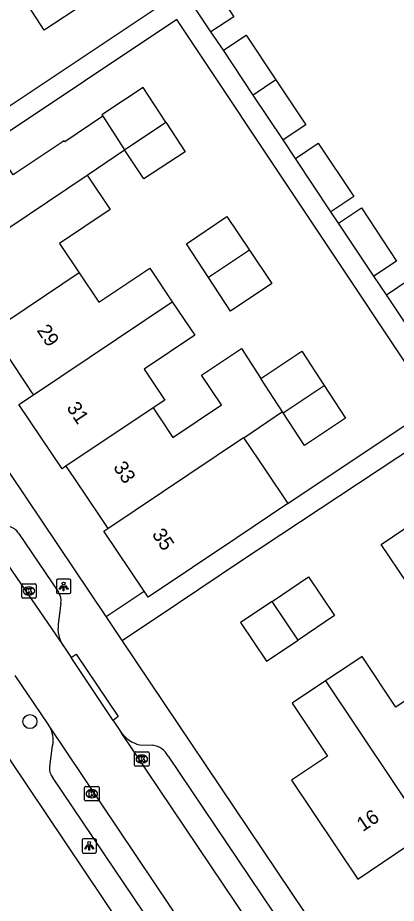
# Model space of a CAD drawing. Extents: x 158352 to 159489, y 383828 to 384597.
# Drawn here: x 158808.6 to 158835, y 384309.4 to 384371.1 of the extents above; entities that cross this region are included whole.
import ezdxf

# ---------------------------------------------------------------- set-up
doc = ezdxf.new("R2010")
doc.units = 0
for name, color, linetype in [('IMGEO_Boom', 7, 'Continuous'), ('IMGEO_Kolk', 7, 'Continuous'), ('IMGEO_Lichtpunt', 7, 'Continuous'), ('IMGEO_Pand', 7, 'Continuous'), ('IMGEO_Pand_nummerreeks', 7, 'Continuous'), ('IMGEO_Rijbaan_lokaal_open', 7, 'Continuous'), ('IMGEO_Voetpad_open', 7, 'Continuous')]:
    doc.layers.add(name, color=color, linetype=linetype)

msp = doc.modelspace()

# ---------------------------------------------------------------- linework, layer by layer
at = {"layer": 'IMGEO_Boom'}
msp.add_circle((158809.47, 384322.081), 0.489, dxfattribs=at)
at = {"layer": 'IMGEO_Kolk'}
for p, q in [((158808.897, 384330.753), (158808.897, 384331.605)), ((158808.972, 384331.679), (158809.824, 384331.679)), ((158809.385, 384331.459), (158809.41, 384331.459)), ((158809.898, 384331.605), (158809.898, 384330.753)), ((158809.824, 384330.679), (158808.972, 384330.679)), ((158809.408, 384330.899), (158809.383, 384330.899)), ((158816.753, 384319.045), (158816.753, 384319.897)), ((158816.828, 384319.971), (158817.68, 384319.971)), ((158817.241, 384319.751), (158817.266, 384319.751)), ((158817.754, 384319.897), (158817.754, 384319.045)), ((158817.68, 384318.971), (158816.828, 384318.971)), ((158817.264, 384319.191), (158817.239, 384319.191)), ((158813.273, 384316.63), (158813.273, 384317.482)), ((158813.348, 384317.556), (158814.2, 384317.556)), ((158813.761, 384317.336), (158813.786, 384317.336)), ((158814.274, 384317.482), (158814.274, 384316.63)), ((158814.2, 384316.556), (158813.348, 384316.556)), ((158813.784, 384316.776), (158813.759, 384316.776))]:
    msp.add_line(p, q, dxfattribs=at)
for points in [[(158808.897, 384330.753), (158808.897, 384331.605)], [(158808.972, 384331.679), (158809.824, 384331.679)], [(158809.218, 384331.379), (158809.341, 384331.379), (158809.341, 384331.228), (158809.471, 384331.379), (158809.635, 384331.379), (158809.489, 384331.228), (158809.642, 384330.979), (158809.49, 384330.979), (158809.405, 384331.143), (158809.341, 384331.076), (158809.341, 384330.979), (158809.218, 384330.979), (158809.218, 384331.379)], [(158809.898, 384331.605), (158809.898, 384330.753)], [(158809.824, 384330.679), (158808.972, 384330.679)], [(158816.753, 384319.045), (158816.753, 384319.897)], [(158816.828, 384319.971), (158817.68, 384319.971)], [(158817.074, 384319.671), (158817.197, 384319.671), (158817.197, 384319.52), (158817.327, 384319.671), (158817.491, 384319.671), (158817.345, 384319.52), (158817.498, 384319.271), (158817.346, 384319.271), (158817.261, 384319.435), (158817.197, 384319.368), (158817.197, 384319.271), (158817.074, 384319.271), (158817.074, 384319.671)], [(158817.754, 384319.897), (158817.754, 384319.045)], [(158817.68, 384318.971), (158816.828, 384318.971)], [(158813.273, 384316.63), (158813.273, 384317.482)], [(158813.348, 384317.556), (158814.2, 384317.556)], [(158813.594, 384317.256), (158813.717, 384317.256), (158813.717, 384317.105), (158813.847, 384317.256), (158814.011, 384317.256), (158813.865, 384317.105), (158814.018, 384316.856), (158813.866, 384316.856), (158813.781, 384317.02), (158813.717, 384316.953), (158813.717, 384316.856), (158813.594, 384316.856), (158813.594, 384317.256)], [(158814.274, 384317.482), (158814.274, 384316.63)], [(158814.2, 384316.556), (158813.348, 384316.556)]]:
    msp.add_lwpolyline(points, dxfattribs=at)
for centre, start, end in [((158808.974, 384331.603), 91.55205, 178.44795), ((158808.974, 384331.603), 91.55205, 178.44795), ((158809.822, 384331.603), 1.55205, 88.44795), ((158809.822, 384331.603), 1.55205, 88.44795), ((158808.974, 384330.755), 181.55205, 268.44795), ((158808.974, 384330.755), 181.55205, 268.44795), ((158809.822, 384330.755), 271.55205, 358.44795), ((158809.822, 384330.755), 271.55205, 358.44795), ((158816.83, 384319.895), 91.55205, 178.44795), ((158816.83, 384319.895), 91.55205, 178.44795), ((158817.678, 384319.895), 1.55205, 88.44795), ((158817.678, 384319.895), 1.55205, 88.44795), ((158816.83, 384319.047), 181.55205, 268.44795), ((158816.83, 384319.047), 181.55205, 268.44795), ((158817.678, 384319.047), 271.55205, 358.44795), ((158817.678, 384319.047), 271.55205, 358.44795), ((158813.35, 384317.48), 91.55205, 178.44795), ((158813.35, 384317.48), 91.55205, 178.44795), ((158814.198, 384317.48), 1.55205, 88.44795), ((158814.198, 384317.48), 1.55205, 88.44795), ((158813.35, 384316.632), 181.55205, 268.44795), ((158813.35, 384316.632), 181.55205, 268.44795), ((158814.198, 384316.632), 271.55205, 358.44795), ((158814.198, 384316.632), 271.55205, 358.44795)]:
    msp.add_arc(centre, 0.0765, start, end, dxfattribs=at)
for centre, major_axis, ratio, start_param, end_param in [((158809.384, 384331.179), (-0.387, 0.002), 0.722429, 4.712389, 7.853982), ((158809.409, 384331.179), (-0.39, 0.002), 0.717154, 1.570796, 4.712389), ((158817.24, 384319.471), (-0.387, 0.002), 0.722429, 4.712389, 7.853982), ((158817.265, 384319.471), (-0.39, 0.002), 0.717154, 1.570796, 4.712389), ((158813.76, 384317.056), (-0.387, 0.002), 0.722429, 4.712389, 7.853982), ((158813.785, 384317.056), (-0.39, 0.002), 0.717154, 1.570796, 4.712389)]:
    msp.add_ellipse(centre, major_axis=major_axis, ratio=ratio, start_param=start_param, end_param=end_param, dxfattribs=at)
at = {"layer": 'IMGEO_Lichtpunt'}
for p, q in [((158811.314, 384331.899), (158811.314, 384331.092)), ((158811.314, 384331.899), (158811.314, 384331.092)), ((158812.216, 384331.994), (158811.408, 384331.994)), ((158812.216, 384331.994), (158811.408, 384331.994)), ((158812.31, 384331.092), (158812.31, 384331.899)), ((158812.31, 384331.092), (158812.31, 384331.899)), ((158811.408, 384330.998), (158812.216, 384330.998)), ((158811.408, 384330.998), (158812.216, 384330.998)), ((158813.093, 384313.829), (158813.093, 384313.022)), ((158813.093, 384313.829), (158813.093, 384313.022)), ((158813.995, 384313.924), (158813.187, 384313.924)), ((158813.995, 384313.924), (158813.187, 384313.924)), ((158814.089, 384313.022), (158814.089, 384313.829)), ((158814.089, 384313.022), (158814.089, 384313.829)), ((158813.187, 384312.928), (158813.995, 384312.928)), ((158813.187, 384312.928), (158813.995, 384312.928))]:
    msp.add_line(p, q, dxfattribs=at)
for points in [[(158811.688, 384331.563), (158811.727, 384331.535), (158811.539, 384331.273), (158811.501, 384331.3), (158811.688, 384331.563)], [(158811.79, 384331.515), (158811.837, 384331.515), (158811.837, 384331.193), (158811.79, 384331.193), (158811.79, 384331.515)], [(158811.9, 384331.535), (158811.938, 384331.562), (158812.125, 384331.3), (158812.086, 384331.272), (158811.9, 384331.535)], [(158813.467, 384313.493), (158813.506, 384313.465), (158813.318, 384313.203), (158813.28, 384313.23), (158813.467, 384313.493)], [(158813.569, 384313.445), (158813.616, 384313.445), (158813.616, 384313.123), (158813.569, 384313.123), (158813.569, 384313.445)], [(158813.679, 384313.465), (158813.717, 384313.492), (158813.904, 384313.23), (158813.865, 384313.202), (158813.679, 384313.465)]]:
    msp.add_lwpolyline(points, dxfattribs=at)
for centre in [(158811.813, 384331.697), (158813.592, 384313.627)]:
    msp.add_circle(centre, 0.0994, dxfattribs=at)
for centre, start, end in [((158811.408, 384331.899), 90, 180), ((158811.408, 384331.899), 90, 180), ((158812.216, 384331.899), 0, 90), ((158812.216, 384331.899), 0, 90), ((158811.408, 384331.092), 180, 270), ((158811.408, 384331.092), 180, 270), ((158812.216, 384331.092), 270, 0), ((158812.216, 384331.092), 270, 360), ((158813.187, 384313.829), 90, 180), ((158813.187, 384313.829), 90, 180), ((158813.995, 384313.829), 0, 90), ((158813.995, 384313.829), 0, 90), ((158813.187, 384313.022), 180, 270), ((158813.187, 384313.022), 180, 270), ((158813.995, 384313.022), 270, 0), ((158813.995, 384313.022), 270, 360)]:
    msp.add_arc(centre, 0.0946, start, end, dxfattribs=at)
at = {"layer": 'IMGEO_Pand'}
for points in [[(158819.593, 384373.829), (158821.174, 384374.882), (158823.645, 384371.172), (158822.064, 384370.119)], [(158812.002, 384374.182), (158813.347, 384372.13), (158810.465, 384370.24), (158809.136, 384372.267)], [(158822.064, 384370.119), (158819.593, 384373.829)], [(158822.926, 384368.83), (158824.507, 384369.884), (158826.585, 384366.766)], [(158825.004, 384365.712), (158822.926, 384368.83)], [(158826.585, 384366.766), (158825.004, 384365.712)], [(158826.585, 384366.766), (158828.664, 384363.649), (158827.083, 384362.595)], [(158818.92, 384363.831), (158817.345, 384366.234), (158814.463, 384364.344), (158814.533, 384364.237)], [(158827.083, 384362.595), (158825.004, 384365.712)], [(158814.533, 384364.237), (158811.889, 384362.464), (158811.842, 384362.534), (158808.312, 384360.165), (158806.819, 384362.39)], [(158814.533, 384364.237), (158816.058, 384361.91)], [(158818.92, 384363.831), (158820.273, 384361.767), (158817.391, 384359.877), (158816.058, 384361.91)], [(158816.058, 384361.91), (158818.92, 384363.831)], [(158827.944, 384361.301), (158829.525, 384362.354), (158831.998, 384358.64), (158830.416, 384357.587)], [(158813.447, 384360.142), (158816.058, 384361.91)], [(158830.416, 384357.587), (158827.944, 384361.301)], [(158803.801, 384353.669), (158813.447, 384360.142)], [(158813.447, 384360.142), (158815.052, 384357.751), (158811.52, 384355.381), (158812.896, 384353.331)], [(158830.948, 384356.8), (158832.531, 384357.85), (158834.982, 384354.156), (158833.399, 384353.105)], [(158821.893, 384353.01), (158820.352, 384355.361), (158823.169, 384357.252), (158824.736, 384354.918)], [(158833.399, 384353.105), (158830.948, 384356.8)], [(158824.736, 384354.918), (158821.893, 384353.01)], [(158824.736, 384354.918), (158826.302, 384352.584), (158823.435, 384350.66), (158821.893, 384353.01)], [(158812.896, 384353.331), (158814.271, 384351.281), (158817.804, 384353.652), (158819.37, 384351.318)], [(158812.896, 384353.331), (158806.773, 384349.222)], [(158834.269, 384351.81), (158835.851, 384352.863), (158838.311, 384349.167), (158836.729, 384348.114)], [(158836.729, 384348.114), (158834.269, 384351.81)], [(158809.706, 384344.833), (158819.37, 384351.318)], [(158819.37, 384351.318), (158820.937, 384348.984), (158817.411, 384346.618), (158818.848, 384344.476), (158818.035, 384343.93)], [(158806.773, 384349.222), (158809.208, 384345.578), (158809.603, 384344.987), (158809.706, 384344.833)], [(158818.035, 384343.93), (158818.273, 384343.576), (158818.543, 384343.173), (158819.416, 384341.872), (158822.8, 384344.143), (158821.412, 384346.196), (158824.183, 384348.056), (158825.531, 384345.981)], [(158825.531, 384345.981), (158828.382, 384347.884), (158829.941, 384345.484)], [(158827.046, 384343.649), (158825.531, 384345.981)], [(158827.095, 384343.574), (158829.941, 384345.484)], [(158829.941, 384345.484), (158831.42, 384343.209), (158828.569, 384341.306), (158827.095, 384343.574)], [(158811.976, 384339.864), (158811.702, 384339.68), (158808.701, 384344.158), (158809.706, 384344.833)], [(158818.035, 384343.93), (158811.976, 384339.864)], [(158827.046, 384343.649), (158824.353, 384341.828)], [(158827.095, 384343.574), (158827.046, 384343.649)], [(158814.887, 384335.528), (158824.329, 384341.864), (158824.353, 384341.828)], [(158824.353, 384341.828), (158825.858, 384339.586), (158827.419, 384337.261)], [(158811.976, 384339.864), (158812.564, 384338.988), (158814.379, 384336.285), (158814.887, 384335.528)], [(158827.419, 384337.261), (158823.857, 384334.879), (158817.688, 384330.754), (158817.406, 384331.174)], [(158838.049, 384333.369), (158835.683, 384331.774), (158833.906, 384334.408), (158836.281, 384336.009)], [(158817.406, 384331.174), (158814.613, 384335.344), (158814.887, 384335.528)], [(158826.316, 384330.453), (158828.862, 384332.161), (158830.672, 384329.465), (158828.124, 384327.754)], [(158826.316, 384330.453), (158824.127, 384328.985), (158825.939, 384326.287), (158828.124, 384327.754)], [(158828.124, 384327.754), (158826.316, 384330.453)], [(158837.727, 384323.633), (158837.112, 384324.549), (158834.938, 384323.093), (158832.579, 384326.616), (158831.863, 384326.137), (158830.029, 384324.909)], [(158830.029, 384324.909), (158827.708, 384323.354), (158830.177, 384319.666), (158827.677, 384317.992), (158832.282, 384311.116), (158835.796, 384313.469), (158837.004, 384314.278), (158837.104, 384314.345)], [(158830.029, 384324.909), (158837.104, 384314.345)]]:
    msp.add_lwpolyline(points, dxfattribs=at)
at = {"layer": 'IMGEO_Rijbaan_lokaal_open'}
for points in [[(158805.266, 384336.856), (158811.777, 384327.369)], [(158811.777, 384327.369), (158812.331, 384326.54)], [(158815.256, 384322.165), (158812.331, 384326.54)], [(158810.808, 384321.782), (158810.734, 384321.892), (158808.448, 384325.282)], [(158815.256, 384322.165), (158815.814, 384321.331)], [(158824.147, 384301.902), (158810.808, 384321.782)], [(158827.398, 384304.097), (158815.814, 384321.331)]]:
    msp.add_lwpolyline(points, dxfattribs=at)
at = {"layer": 'IMGEO_Voetpad_open'}
for points in [[(158805.842, 384363.496), (158818.889, 384372.181), (158812.03, 384382.486), (158800.915, 384399.099), (158797.336, 384396.74), (158786.985, 384389.919)], [(158827.419, 384337.261), (158837.601, 384344.069), (158819.7, 384370.964), (158806.819, 384362.39)], [(158822.926, 384368.83), (158822.064, 384370.119)], [(158827.944, 384361.301), (158827.083, 384362.595)], [(158830.948, 384356.8), (158830.416, 384357.587)], [(158814.765, 384329.403), (158797.039, 384355.828)], [(158815.887, 384327.73), (158819.74, 384330.315), (158824.183, 384333.296), (158837.811, 384342.305), (158841.36, 384341.527), (158861.458, 384355.013), (158867.819, 384345.532), (158868.637, 384346.081)], [(158834.269, 384351.81), (158833.399, 384353.105)], [(158808.666, 384335.207), (158811.466, 384331.092)], [(158814.765, 384329.403), (158817.406, 384331.174)], [(158811.626, 384330.323), (158811.443, 384328.87)], [(158815.887, 384327.73), (158814.765, 384329.403)], [(158831.561, 384304.365), (158815.887, 384327.73)], [(158812.331, 384326.54), (158812.673, 384326.776), (158815.61, 384322.434), (158815.256, 384322.165)], [(158806.635, 384321.537), (158806.727, 384321.4), (158822.323, 384298.139)], [(158810.845, 384318.965), (158811.046, 384320.385)], [(158817.088, 384320.458), (158818.01, 384320.435)], [(158819.092, 384319.664), (158827.2, 384307.604)], [(158821.011, 384303.412), (158811.045, 384318.206)]]:
    msp.add_lwpolyline(points, dxfattribs=at)
for centre, radius, start, end in [((158807.87, 384334.758), 0.913, 29.42695, 80.44583), ((158810.406, 384330.47), 1.229, 353.12034, 30.38649), ((158813.509, 384328.542), 2.092, 170.97936, 214.11059), ((158809.215, 384320.792), 1.875, 347.47055, 31.8662), ((158817.705, 384322.725), 2.35, 216.394, 254.76474), ((158817.798, 384318.993), 1.457, 27.40296, 81.65203), ((158811.73, 384318.792), 0.902, 168.96837, 220.55591)]:
    msp.add_arc(centre, radius, start, end, dxfattribs=at)

# ---------------------------------------------------------------- texts
at = {"layer": 'IMGEO_Pand_nummerreeks'}
for s, rotation, p in [('29', 303.8616, (158809.916, 384349.326)), ('31', 303.86732, (158811.979, 384343.943)), ('33', 303.86732, (158815.227, 384339.797)), ('35', 303.85014, (158817.923, 384335.125)), ('16', 33.81024, (158832.63, 384314.382))]:
    msp.add_text(s, height=1, rotation=rotation, dxfattribs=at).set_placement(p)

doc.saveas('drawing.dxf')
